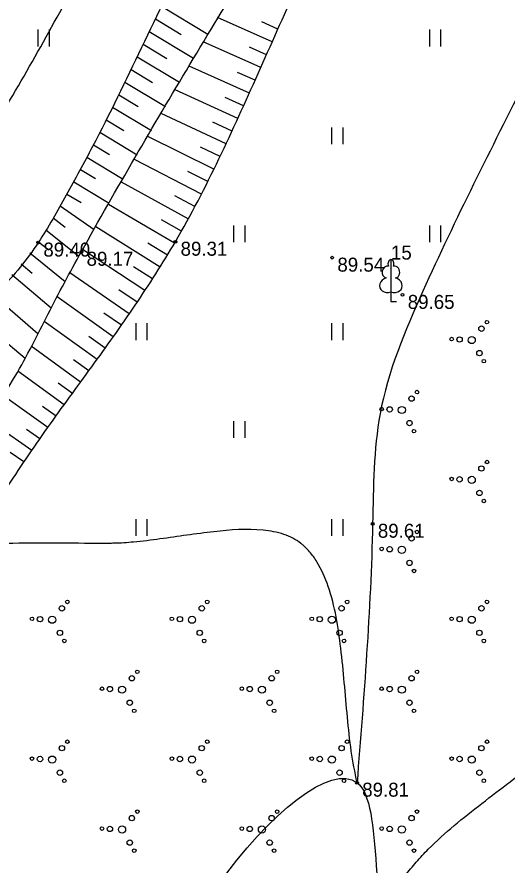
# Model space of a CAD drawing. Extents: x 635228 to 635525, y 248590 to 248800.
# Drawn here: x 635361.24 to 635378.76, y 248708.73 to 248739.05 of the extents above; entities that cross this region are included whole.
import ezdxf

# ---------------------------------------------------------------- set-up
doc = ezdxf.new("R2010")
doc.units = 0
for name, color, linetype in [('RELJ_AATZ_####_TKST_#', 7, 'Continuous'), ('RELJ_ELEM_####_####_#', 7, 'Continuous'), ('RELJ_HORZ_PAMT_####_#', 7, 'Continuous'), ('RELJ_HORZ_RESN_####_#', 7, 'Continuous'), ('RELJ_NOGA_####_####_#', 7, 'Continuous'), ('RELJ_NOGL_####_####_#', 7, 'Continuous'), ('TERT_DIAM_####_TKST_#', 7, 'Continuous'), ('TERT_ELEM_####_####_#', 7, 'Continuous'), ('TERT_KONT_####_####_#', 7, 'Continuous')]:
    doc.layers.add(name, color=color, linetype=linetype)

msp = doc.modelspace()

# ---------------------------------------------------------------- linework, layer by layer
at = {"layer": 'RELJ_ELEM_####_####_#'}
for centre in [(635362, 248730.984), (635366.906, 248731.015), (635363.546, 248730.656), (635372.511, 248730.446), (635375.027, 248729.114), (635373.958, 248720.932), (635373.4, 248711.674)]:
    msp.add_circle(centre, 0.05, dxfattribs=at)
at = {"layer": 'RELJ_HORZ_PAMT_####_#'}
msp.add_spline([(635330.297, 248677.354), (635331.177, 248678.319), (635332.06, 248679.489), (635332.793, 248680.772), (635333.481, 248682.089), (635334.226, 248683.36), (635335.284, 248684.77), (635336.431, 248686.125), (635337.538, 248687.508), (635338.035, 248688.237), (635338.472, 248689.004), (635339.583, 248691.554), (635340.487, 248694.188), (635341.335, 248696.84), (635341.787, 248698.153), (635342.281, 248699.447), (635343.206, 248701.423), (635344.222, 248703.369), (635345.157, 248705.345), (635345.54, 248706.364), (635345.837, 248707.412), (635346.445, 248710.352), (635346.944, 248713.307), (635347.835, 248719.233), (635348.116, 248721.113), (635348.378, 248722.995), (635348.645, 248724.878), (635348.937, 248726.758), (635349.503, 248728.159), (635350.332, 248729.539), (635351.235, 248730.852), (635351.672, 248731.412), (635352.153, 248731.934), (635352.67, 248732.415), (635353.216, 248732.849), (635353.585, 248732.808), (635353.973, 248732.393), (635354.375, 248731.871), (635354.581, 248731.654), (635354.79, 248731.511), (635355.514, 248731.162), (635356.357, 248730.815), (635357.156, 248730.69), (635357.748, 248731.008), (635358.207, 248731.666), (635358.657, 248732.33), (635359.531, 248733.675), (635361.193, 248736.42), (635362.771, 248739.216), (635364.301, 248742.038), (635372.089, 248756.526)], degree=3, dxfattribs=at)
at = {"layer": 'RELJ_HORZ_RESN_####_#'}
msp.add_spline([(635370.286, 248702.191), (635371.268, 248702.893), (635371.931, 248703.448), (635372.235, 248703.758), (635372.523, 248704.086), (635373.233, 248705.103), (635373.842, 248706.207), (635374.44, 248707.318), (635375.119, 248708.351), (635375.519, 248708.837), (635375.945, 248709.297), (635376.871, 248710.138), (635378.872, 248711.708), (635380.875, 248713.355), (635381.799, 248714.3), (635382.631, 248715.376), (635384.271, 248718.308), (635385.412, 248721.331), (635386.184, 248724.417), (635386.472, 248725.973), (635386.718, 248727.534), (635386.765, 248728.402), (635386.702, 248729.274), (635386.549, 248730.144), (635386.323, 248731.007), (635386.319, 248731.019)], degree=3, dxfattribs=at)
at = {"layer": 'RELJ_NOGA_####_####_#'}
for p, q in [((635366.41, 248739.438), (635368.062, 248738.443)), ((635366.191, 248738.986), (635367.116, 248738.43)), ((635370.367, 248738.159), (635368.407, 248739.035)), ((635370.572, 248738.615), (635370, 248738.873)), ((635365.973, 248738.534), (635367.558, 248737.58)), ((635369.959, 248737.246), (635367.899, 248738.165)), ((635365.756, 248738.081), (635366.603, 248737.571)), ((635370.163, 248737.702), (635369.56, 248737.972)), ((635365.538, 248737.629), (635367.054, 248736.716)), ((635369.551, 248736.333), (635367.394, 248737.299)), ((635365.319, 248737.177), (635366.091, 248736.712)), ((635369.755, 248736.789), (635369.122, 248737.071)), ((635365.1, 248736.725), (635366.55, 248735.852)), ((635369.139, 248735.422), (635366.897, 248736.447)), ((635364.879, 248736.274), (635365.579, 248735.853)), ((635369.345, 248735.877), (635368.685, 248736.175)), ((635364.657, 248735.824), (635366.046, 248734.988)), ((635368.718, 248734.514), (635366.402, 248735.599)), ((635364.433, 248735.376), (635365.067, 248734.994)), ((635368.93, 248734.967), (635368.246, 248735.285)), ((635364.207, 248734.928), (635365.544, 248734.123)), ((635368.286, 248733.613), (635365.921, 248734.773)), ((635363.977, 248734.483), (635364.555, 248734.135)), ((635368.503, 248734.063), (635367.801, 248734.399)), ((635363.745, 248734.039), (635365.042, 248733.258)), ((635367.837, 248732.719), (635365.447, 248733.956)), ((635363.51, 248733.597), (635364.044, 248733.275)), ((635368.063, 248733.165), (635367.349, 248733.524)), ((635363.271, 248733.157), (635364.542, 248732.392)), ((635367.368, 248731.836), (635364.977, 248733.145)), ((635363.028, 248732.72), (635363.533, 248732.416)), ((635367.605, 248732.276), (635366.886, 248732.656)), ((635362.787, 248732.296), (635364.001, 248731.451)), ((635366.877, 248730.965), (635364.517, 248732.349)), ((635362.537, 248731.868), (635362.964, 248731.542)), ((635367.126, 248731.398), (635366.411, 248731.8)), ((635366.359, 248730.109), (635364.056, 248731.546)), ((635362.279, 248731.437), (635363.455, 248730.495)), ((635362.018, 248731.006), (635362.376, 248730.723)), ((635366.621, 248730.535), (635365.922, 248730.961)), ((635361.705, 248730.616), (635362.961, 248729.594)), ((635365.818, 248729.268), (635363.59, 248730.733)), ((635361.387, 248730.231), (635361.784, 248729.897)), ((635366.091, 248729.687), (635365.411, 248730.124)), ((635361.064, 248729.849), (635362.468, 248728.653)), ((635365.259, 248728.439), (635363.128, 248729.902)), ((635360.412, 248729.091), (635361.99, 248727.731)), ((635365.54, 248728.852), (635364.886, 248729.293)), ((635364.686, 248727.619), (635362.674, 248729.048)), ((635364.974, 248728.028), (635364.352, 248728.464)), ((635359.764, 248728.329), (635361.532, 248726.858)), ((635364.105, 248726.806), (635362.217, 248728.167)), ((635364.396, 248727.212), (635363.811, 248727.63)), ((635363.518, 248725.996), (635361.753, 248727.277)), ((635363.812, 248726.401), (635363.264, 248726.797)), ((635362.931, 248725.187), (635361.275, 248726.385)), ((635363.224, 248725.592), (635362.712, 248725.963)), ((635362.348, 248724.374), (635360.755, 248725.508)), ((635362.639, 248724.781), (635362.154, 248725.129)), ((635361.772, 248723.557), (635360.163, 248724.668)), ((635362.059, 248723.966), (635361.581, 248724.302)), ((635361.489, 248723.144), (635360.997, 248723.481))]:
    msp.add_line(p, q, dxfattribs=at)
for points in [[(635375.27, 248754.857), (635369.314, 248744.971), (635367.429, 248741.507), (635365.696, 248737.957), (635363.943, 248734.417), (635363.006, 248732.681), (635362, 248730.984), (635361.355, 248730.103), (635360.628, 248729.283), (635359.885, 248728.474), (635359.193, 248727.625), (635357.58, 248725.368), (635356.018, 248723.079), (635353.089, 248718.349), (635349.569, 248710.638), (635349.163, 248709.221), (635348.864, 248707.772), (635348.539, 248706.335), (635348.053, 248704.954), (635343.12, 248694.162), (635337.407, 248681.667), (635331.093, 248670.147), (635326.8, 248663.851)], [(635326.8, 248663.851), (635325.31, 248661.345), (635325.174, 248660.918), (635325.219, 248660.451), (635325.416, 248659.984), (635325.736, 248659.553), (635326.126, 248659.27), (635326.575, 248659.146), (635327.409, 248659.333), (635327.907, 248659.688), (635328.397, 248660.078), (635328.864, 248660.506), (635329.288, 248660.978), (635331.594, 248663.918), (635332.687, 248665.412), (635333.734, 248666.95), (635337.875, 248673.353), (635341.554, 248680.001), (635347.428, 248693.006), (635353.063, 248706.101), (635354.098, 248708.621), (635355.097, 248711.155), (635356.117, 248713.682), (635356.653, 248714.935), (635357.216, 248716.179), (635358.916, 248719.218), (635360.822, 248722.14), (635362.339, 248724.363), (635363.916, 248726.545), (635365.467, 248728.744), (635366.906, 248731.015), (635368.464, 248733.981), (635369.863, 248737.03), (635371.249, 248740.086), (635372.769, 248743.072), (635378.435, 248753.196)]]:
    msp.add_spline(points, degree=3, dxfattribs=at)
at = {"layer": 'RELJ_NOGL_####_####_#'}
msp.add_spline([(635326.936, 248660.713), (635331.766, 248667.928), (635333.88, 248671.254), (635335.853, 248674.668), (635337.706, 248678.153), (635339.464, 248681.691), (635342.12, 248687.391), (635344.65, 248693.14), (635347.108, 248698.916), (635349.548, 248704.698), (635350.777, 248707.84), (635351.91, 248711.022), (635353.067, 248714.195), (635353.692, 248715.764), (635354.368, 248717.312), (635355.034, 248718.536), (635355.835, 248719.677), (635357.677, 248721.811), (635359.567, 248723.919), (635361.176, 248726.206), (635362.355, 248728.434), (635362.939, 248729.551), (635363.546, 248730.656), (635367.422, 248737.348), (635371.307, 248744.035), (635372.506, 248746.487), (635373.579, 248749.023), (635374.785, 248751.459), (635376.384, 248753.612), (635376.807, 248754.05)], degree=3, dxfattribs=at)
at = {"layer": 'TERT_ELEM_####_####_#'}
for p, q in [((635362, 248738), (635362, 248738.6)), ((635362.4, 248738), (635362.4, 248738.6)), ((635376, 248738), (635376, 248738.6)), ((635376.4, 248738), (635376.4, 248738.6)), ((635372.5, 248734.5), (635372.5, 248735.1)), ((635372.9, 248734.5), (635372.9, 248735.1)), ((635369, 248731), (635369, 248731.6)), ((635369.4, 248731), (635369.4, 248731.6)), ((635376, 248731), (635376, 248731.6)), ((635376.4, 248731), (635376.4, 248731.6)), ((635374.612, 248729.224), (635374.612, 248728.877)), ((635374.612, 248728.877), (635374.812, 248728.877)), ((635365.5, 248727.5), (635365.5, 248728.1)), ((635365.9, 248727.5), (635365.9, 248728.1)), ((635372.5, 248727.5), (635372.5, 248728.1)), ((635372.9, 248727.5), (635372.9, 248728.1)), ((635369, 248724), (635369, 248724.6)), ((635369.4, 248724), (635369.4, 248724.6)), ((635365.5, 248720.5), (635365.5, 248721.1)), ((635365.9, 248720.5), (635365.9, 248721.1)), ((635372.5, 248720.5), (635372.5, 248721.1)), ((635372.9, 248720.5), (635372.9, 248721.1))]:
    msp.add_line(p, q, dxfattribs=at)
for points in [[(635374.612, 248730.377), (635374.612, 248729.224)], [(635374.701, 248730.144), (635374.7, 248730.145)]]:
    msp.add_lwpolyline(points, dxfattribs=at)
for centre, radius in [((635378.044, 248728.139), 0.064), ((635377.848, 248727.908), 0.096), ((635376.782, 248727.534), 0.064), ((635377.066, 248727.521), 0.096), ((635377.5, 248727.5), 0.128), ((635377.776, 248727.033), 0.096), ((635377.934, 248726.744), 0.064), ((635375.348, 248725.408), 0.096), ((635375.544, 248725.639), 0.064), ((635374.566, 248725.021), 0.096), ((635375, 248725), 0.128), ((635374.282, 248725.034), 0.064), ((635375.276, 248724.533), 0.096), ((635375.434, 248724.244), 0.064), ((635377.848, 248722.908), 0.096), ((635378.044, 248723.139), 0.064), ((635376.782, 248722.534), 0.064), ((635377.066, 248722.521), 0.096), ((635377.5, 248722.5), 0.128), ((635377.776, 248722.033), 0.096), ((635377.934, 248721.744), 0.064), ((635375.544, 248720.639), 0.064), ((635375.348, 248720.408), 0.096), ((635374.282, 248720.034), 0.064), ((635374.566, 248720.021), 0.096), ((635375, 248720), 0.128), ((635375.276, 248719.533), 0.096), ((635375.434, 248719.244), 0.064), ((635363.044, 248718.139), 0.064), ((635368.044, 248718.139), 0.064), ((635373.044, 248718.139), 0.064), ((635378.044, 248718.139), 0.064), ((635362.848, 248717.908), 0.096), ((635367.848, 248717.908), 0.096), ((635372.848, 248717.908), 0.096), ((635377.848, 248717.908), 0.096), ((635361.782, 248717.534), 0.064), ((635362.066, 248717.521), 0.096), ((635362.5, 248717.5), 0.128), ((635366.782, 248717.534), 0.064), ((635367.066, 248717.521), 0.096), ((635367.5, 248717.5), 0.128), ((635371.782, 248717.534), 0.064), ((635372.066, 248717.521), 0.096), ((635372.5, 248717.5), 0.128), ((635376.782, 248717.534), 0.064), ((635377.066, 248717.521), 0.096), ((635377.5, 248717.5), 0.128), ((635362.776, 248717.033), 0.096), ((635367.776, 248717.033), 0.096), ((635372.776, 248717.033), 0.096), ((635377.776, 248717.033), 0.096), ((635362.934, 248716.744), 0.064), ((635367.934, 248716.744), 0.064), ((635372.934, 248716.744), 0.064), ((635377.934, 248716.744), 0.064), ((635365.348, 248715.408), 0.096), ((635365.544, 248715.639), 0.064), ((635370.348, 248715.408), 0.096), ((635370.544, 248715.639), 0.064), ((635375.348, 248715.408), 0.096), ((635375.544, 248715.639), 0.064), ((635364.566, 248715.021), 0.096), ((635365, 248715), 0.128), ((635369.566, 248715.021), 0.096), ((635370, 248715), 0.128), ((635374.566, 248715.021), 0.096), ((635375, 248715), 0.128), ((635364.282, 248715.034), 0.064), ((635369.282, 248715.034), 0.064), ((635374.282, 248715.034), 0.064), ((635365.276, 248714.533), 0.096), ((635370.276, 248714.533), 0.096), ((635375.276, 248714.533), 0.096), ((635365.434, 248714.244), 0.064), ((635370.434, 248714.244), 0.064), ((635375.434, 248714.244), 0.064), ((635362.848, 248712.908), 0.096), ((635363.044, 248713.139), 0.064), ((635367.848, 248712.908), 0.096), ((635368.044, 248713.139), 0.064), ((635372.848, 248712.908), 0.096), ((635373.044, 248713.139), 0.064), ((635377.848, 248712.908), 0.096), ((635378.044, 248713.139), 0.064), ((635361.782, 248712.534), 0.064), ((635362.066, 248712.521), 0.096), ((635362.5, 248712.5), 0.128), ((635366.782, 248712.534), 0.064), ((635367.066, 248712.521), 0.096), ((635367.5, 248712.5), 0.128), ((635371.782, 248712.534), 0.064), ((635372.066, 248712.521), 0.096), ((635372.5, 248712.5), 0.128), ((635376.782, 248712.534), 0.064), ((635377.066, 248712.521), 0.096), ((635377.5, 248712.5), 0.128), ((635362.776, 248712.033), 0.096), ((635367.776, 248712.033), 0.096), ((635372.776, 248712.033), 0.096), ((635377.776, 248712.033), 0.096), ((635362.934, 248711.744), 0.064), ((635367.934, 248711.744), 0.064), ((635372.934, 248711.744), 0.064), ((635377.934, 248711.744), 0.064), ((635365.544, 248710.639), 0.064), ((635370.544, 248710.639), 0.064), ((635375.544, 248710.639), 0.064), ((635365.348, 248710.408), 0.096), ((635370.348, 248710.408), 0.096), ((635375.348, 248710.408), 0.096), ((635364.282, 248710.034), 0.064), ((635364.566, 248710.021), 0.096), ((635365, 248710), 0.128), ((635369.282, 248710.034), 0.064), ((635369.566, 248710.021), 0.096), ((635370, 248710), 0.128), ((635374.282, 248710.034), 0.064), ((635374.566, 248710.021), 0.096), ((635375, 248710), 0.128), ((635365.276, 248709.533), 0.096), ((635370.276, 248709.533), 0.096), ((635375.276, 248709.533), 0.096), ((635365.434, 248709.244), 0.064), ((635370.434, 248709.244), 0.064), ((635375.434, 248709.244), 0.064)]:
    msp.add_circle(centre, radius, dxfattribs=at)
for centre, major_axis, ratio, start_param, end_param in [((635374.612, 248730.227), (0, -0.15), 0.707107, 3.14537, 5.287485), ((635374.611, 248730.227), (0, -0.15), 0.707107, 0.995701, 3.137816), ((635374.483, 248729.932), (-0.039, -0.212), 0.861323, 3.141593, 6.283185), ((635374.74, 248729.932), (0.039, -0.212), 0.861323, 0, 3.141593), ((635374.522, 248729.47), (0.307, 0.095), 0.814445, 1.570796, 4.752015), ((635374.701, 248729.47), (-0.307, 0.095), 0.814445, 1.531171, 4.712389)]:
    msp.add_ellipse(centre, major_axis=major_axis, ratio=ratio, start_param=start_param, end_param=end_param, dxfattribs=at)
at = {"layer": 'TERT_KONT_####_####_#'}
for points in [[(635379.461, 248736.844), (635375.752, 248729.243), (635374.224, 248724.864), (635373.958, 248720.932), (635373.4, 248711.674)], [(635373.4, 248711.674), (635373.195, 248712.802), (635373.056, 248714.014), (635372.819, 248716.487), (635372.369, 248718.693), (635371.966, 248719.57), (635371.702, 248719.931), (635371.552, 248720.089), (635371.473, 248720.162), (635371.432, 248720.197), (635371.411, 248720.214), (635371.39, 248720.231), (635371.106, 248720.414), (635370.784, 248720.551), (635370.043, 248720.701), (635368.282, 248720.649), (635366.355, 248720.388), (635365.407, 248720.276), (635364.729, 248720.234), (635364.511, 248720.231), (635362.802, 248720.239), (635361.094, 248720.231), (635359.533, 248720.175)], [(635347.944, 248675.14), (635353.969, 248676.317), (635361.548, 248680.892), (635362.735, 248687.694), (635367.699, 248695.072), (635365.801, 248699.259), (635373.4, 248711.674), (635374.835, 248703.881), (635382.868, 248697.463), (635386.085, 248703.415)]]:
    msp.add_spline(points, degree=3, dxfattribs=at)

# ---------------------------------------------------------------- texts
at = {"layer": 'RELJ_AATZ_####_TKST_#'}
for s, p in [(' 89.40', (635362, 248730.484)), (' 89.31', (635366.906, 248730.515)), (' 89.17', (635363.546, 248730.156)), (' 89.54', (635372.511, 248729.946)), (' 89.65', (635375.027, 248728.614)), (' 89.61', (635373.958, 248720.432)), (' 89.81', (635373.4, 248711.174))]:
    msp.add_text(s, height=0.5, dxfattribs=at).set_placement(p)
at = {"layer": 'TERT_DIAM_####_TKST_#'}
msp.add_text('15', height=0.5, dxfattribs=at).set_placement((635374.612, 248730.377))

doc.saveas('drawing.dxf')
